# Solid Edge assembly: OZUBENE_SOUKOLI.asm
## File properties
Author: Acer
Template: ISO Metric Assembly.asm
Last saved by: Acer
Revision: 3
Application: Solid Edge
Username: Acer
Typ obsahu dokumentu: 1
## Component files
pastorek.par
prevodove_kolo.par
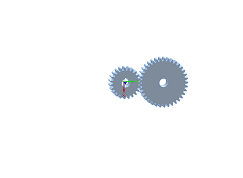
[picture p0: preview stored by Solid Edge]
